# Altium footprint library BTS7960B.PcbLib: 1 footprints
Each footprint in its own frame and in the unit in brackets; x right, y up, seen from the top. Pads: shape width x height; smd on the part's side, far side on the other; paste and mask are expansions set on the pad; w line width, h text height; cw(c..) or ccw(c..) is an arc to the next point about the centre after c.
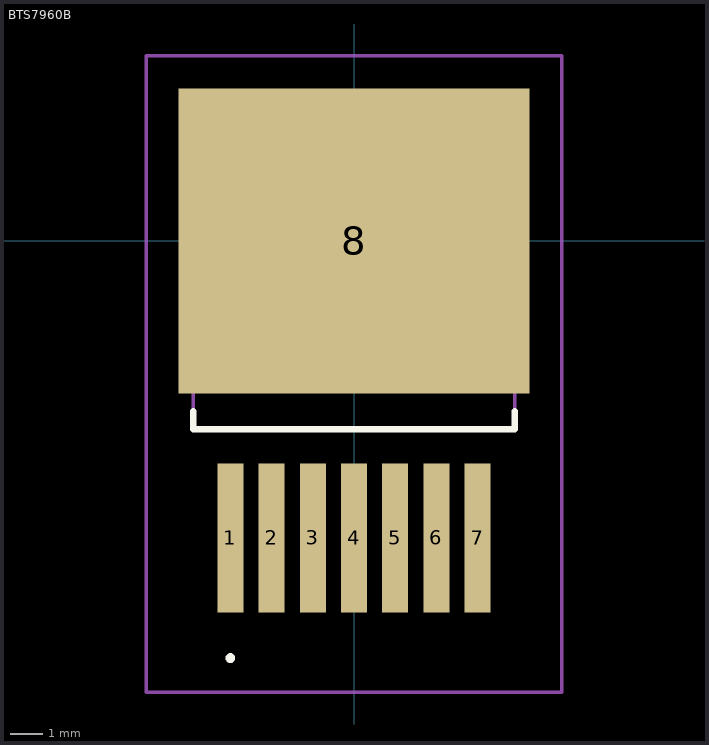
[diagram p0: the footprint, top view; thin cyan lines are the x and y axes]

## BTS7960B [mm]
pads (8):
  rect 0.8x4.6 smd: 1(-3.81,-9.15) 2(-2.54,-9.15) 3(-1.27,-9.15) 4(0,-9.15) 5(1.27,-9.15) 6(2.54,-9.15) 7(3.81,-9.15)
  rect 10.8x9.4 smd: 8(0,0)
Top Overlay:
  lines w0.2: -4.95,-5.8 4.95,-5.8 ; -4.95,-5.8 4.95,-5.8 ; -4.95,-5.8 -4.95,-5.8 ; -4.95,-5.75 -4.95,-5.25 ; -4.95,-5.75 -4.95,-5.75 ; -4.95,-5.75 -4.95,-5.25 ; -4.95,-5.25 -4.95,-5.25 ; -3.81,-12.9 -3.81,-12.9 ; -3.81,-12.9 ccw(c-3.81,-12.85) -3.81,-12.8 ; -3.81,-12.9 cw(c-3.81,-12.85) -3.81,-12.8 ; -3.81,-12.9 -3.81,-12.9 ; -3.81,-12.9 ccw(c-3.81,-12.85) -3.81,-12.8 ; -3.81,-12.8 -3.81,-12.8 ; 4.95,-5.8 4.95,-5.8 ; 4.95,-5.8 4.95,-5.8 ; 4.95,-5.8 4.95,-5.25 ; 4.95,-5.8 4.95,-5.25 ; 4.95,-5.25 4.95,-5.25
Mechanical 15:
  lines w0.1: -4.95,-5.8 4.95,-5.8 4.95,3.4 -4.95,3.4 -4.95,-5.8
Mechanical 20:
  lines w0.1: -6.4,-13.9 6.4,-13.9 6.4,5.7 -6.4,5.7 -6.4,-13.9
3D body "BTS7960B.stp": height 5.8, standoff -4.65, extent -10,-3.376 10,3.376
